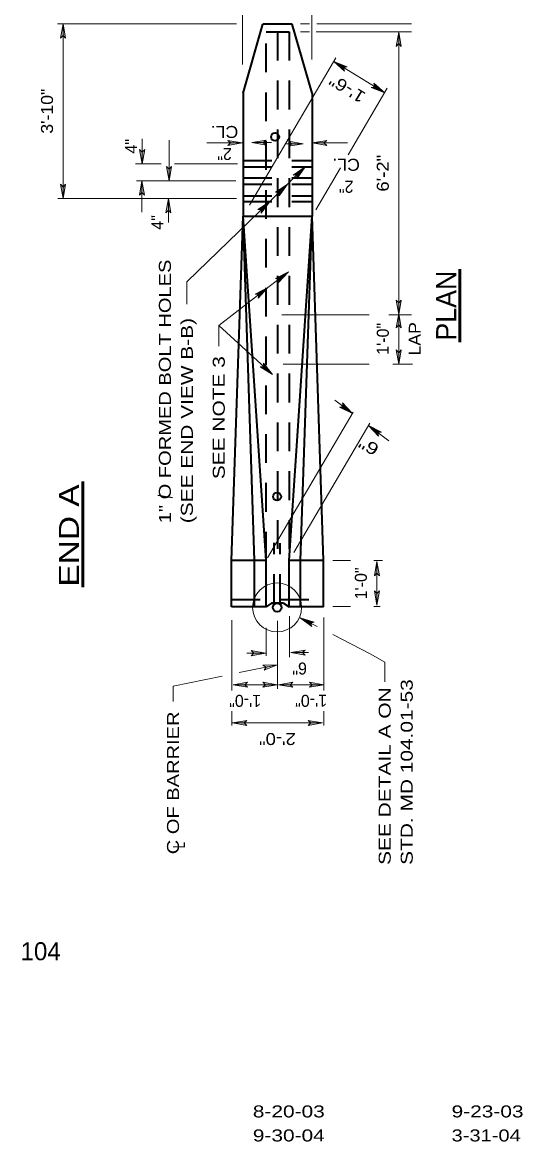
# Model space of a CAD drawing. Extents: x 12.6 to 19.4, y 6.1 to 16.3.
# Drawn here: x 12.57 to 15.07, y 6.25 to 11.84 of the extents above; entities that cross this region are included whole.
import ezdxf
from ezdxf.enums import TextEntityAlignment as Align

# ---------------------------------------------------------------- set-up
doc = ezdxf.new("R2010")
doc.units = 0
doc.header["$LTSCALE"] = 0.024
doc.linetypes.add('LONG_DASHED', pattern=[7.5, 6, -1.5])
for name, color, linetype, lineweight in [('1', 7, 'Continuous', 35), ('10', 7, 'Continuous', 13), ('12', 7, 'Continuous', 53), ('13', 7, 'Continuous', 53)]:
    doc.layers.add(name, color=color, linetype=linetype, lineweight=lineweight)

msp = doc.modelspace()

# ---------------------------------------------------------------- hatches: boundary and pattern name
at = {"layer": '10'}
for points in [[(12.7624, 11.7651), (12.775, 11.8366), (12.7876, 11.7651), (12.775, 11.7786)], [(14.4403, 11.724), (14.4529, 11.7955), (14.4655, 11.724), (14.4529, 11.7375)], [(14.1823, 11.6), (14.128, 11.6482), (14.1955, 11.6215), (14.1774, 11.6178)], [(14.3284, 11.5397), (14.3827, 11.4915), (14.3152, 11.5182), (14.3333, 11.5219)], [(13.5988, 11.2538), (13.6703, 11.2412), (13.5988, 11.2286), (13.6123, 11.2412)], [(13.7894, 11.2304), (13.7179, 11.243), (13.7894, 11.2556), (13.7759, 11.243)], [(13.9038, 11.2503), (13.9753, 11.2377), (13.9038, 11.2251), (13.9173, 11.2377)], [(14.0926, 11.2286), (14.0211, 11.2412), (14.0926, 11.2538), (14.0791, 11.2412)], [(13.1831, 11.2089), (13.1705, 11.1374), (13.1579, 11.2089), (13.1705, 11.1954)], [(13.3179, 11.1235), (13.3053, 11.052), (13.2927, 11.1235), (13.3053, 11.11)], [(13.9256, 11.0809), (13.9857, 11.1216), (13.9431, 11.0628), (13.9441, 11.0812)], [(12.7876, 11.0346), (12.775, 10.9631), (12.7624, 11.0346), (12.775, 11.0211)], [(13.1569, 10.9805), (13.1695, 11.052), (13.1821, 10.9805), (13.1695, 10.994)], [(13.8372, 10.9952), (13.8973, 11.0359), (13.8547, 10.9771), (13.8557, 10.9955)], [(13.2889, 10.8916), (13.3015, 10.9631), (13.3141, 10.8916), (13.3015, 10.9051)], [(13.7478, 10.9085), (13.8079, 10.9492), (13.7653, 10.8904), (13.7662, 10.9088)], [(13.8366, 10.5636), (13.9012, 10.5967), (13.8518, 10.5435), (13.855, 10.5617)], [(13.7348, 10.4854), (13.799, 10.5193), (13.7503, 10.4655), (13.7532, 10.4837)], [(14.4655, 10.4559), (14.4529, 10.3844), (14.4403, 10.4559), (14.4529, 10.4424)], [(14.4403, 10.3182), (14.4529, 10.3897), (14.4655, 10.3182), (14.4529, 10.3317)], [(14.4655, 10.2068), (14.4529, 10.1353), (14.4403, 10.2068), (14.4529, 10.1933)], [(13.7776, 10.1417), (13.822, 10.0843), (13.7606, 10.1231), (13.7791, 10.1233)], [(14.1716, 9.9421), (14.2215, 9.8893), (14.1566, 9.9219), (14.175, 9.9239)], [(14.3513, 9.7767), (14.3016, 9.8296), (14.3664, 9.7969), (14.3481, 9.7949)], [(14.3308, 9.0777), (14.3434, 9.1492), (14.356, 9.0777), (14.3434, 9.0912)], [(14.356, 9.0035), (14.3434, 8.932), (14.3308, 9.0035), (14.3434, 8.99)], [(14.0184, 8.8249), (13.9607, 8.869), (14.03, 8.8473), (14.0122, 8.8423)], [(13.7147, 8.7045), (13.7862, 8.6919), (13.7147, 8.6793), (13.7282, 8.6919)], [(13.9855, 8.6825), (13.914, 8.6951), (13.9855, 8.7077), (13.972, 8.6951)], [(13.7743, 8.6323), (13.8469, 8.6344), (13.7794, 8.6077), (13.7901, 8.6227)], [(13.6964, 8.5213), (13.6249, 8.5339), (13.6964, 8.5465), (13.6829, 8.5339)], [(13.7737, 8.5465), (13.8452, 8.5339), (13.7737, 8.5213), (13.7872, 8.5339)], [(13.9232, 8.5213), (13.8517, 8.5339), (13.9232, 8.5465), (13.9097, 8.5339)], [(14.0064, 8.5465), (14.0779, 8.5339), (14.0064, 8.5213), (14.0199, 8.5339)], [(13.6932, 8.3305), (13.6217, 8.3431), (13.6932, 8.3557), (13.6797, 8.3431)], [(13.9998, 8.3557), (14.0713, 8.3431), (13.9998, 8.3305), (14.0133, 8.3431)]]:
    msp.add_hatch(color=256, dxfattribs=at).paths.add_polyline_path(points)

# ---------------------------------------------------------------- linework, layer by layer
at = {"layer": '1'}
for p, q in [((13.6744, 11.4896), (13.7734, 11.8351)), ((13.9206, 11.8351), (13.7743, 11.8351)), ((14.0198, 11.4896), (13.9206, 11.8351)), ((14.0198, 11.4896), (14.0198, 10.8755)), ((13.7895, 9.1542), (13.6744, 10.8755)), ((13.9047, 9.1542), (14.0198, 10.8755)), ((13.9622, 9.1542), (14.0198, 10.8755)), ((13.7895, 9.1542), (13.6168, 9.1542)), ((13.7895, 8.9239), (13.7895, 9.1542)), ((13.9047, 8.9239), (13.9047, 9.1542)), ((14.0773, 9.1542), (13.9108, 9.1542)), ((13.9622, 8.9239), (13.9622, 9.1542)), ((13.7895, 8.9239), (13.6168, 8.9239)), ((13.8767, 8.9424), (13.8471, 8.9424)), ((13.8767, 8.9424), (13.9047, 8.9239)), ((14.0773, 8.9239), (13.9047, 8.9239))]:
    msp.add_line(p, q, dxfattribs=at)
at = {"layer": '1', "linetype": 'LONG_DASHED'}
for p, q in [((13.8471, 11.7968), (13.8471, 9.1542)), ((13.6744, 11.1536), (14.0198, 11.1536)), ((13.6744, 11.1224), (14.0198, 11.1224)), ((13.6744, 11.067), (14.0198, 11.067)), ((13.6744, 11.0359), (14.0198, 11.0359)), ((13.6744, 10.977), (14.0198, 10.977)), ((13.6744, 10.9492), (14.0198, 10.9492)), ((13.8302, 8.9424), (13.8302, 9.2428)), ((13.8596, 8.9424), (13.8596, 9.2416)), ((13.6158, 8.9593), (14.0773, 8.9593))]:
    msp.add_line(p, q, dxfattribs=at)
msp.add_lwpolyline([(13.7895, 9.1542), (13.7895, 11.7968), (13.9047, 11.7968), (13.9047, 9.1542)], dxfattribs=at)
at = {"layer": '1'}
for points in [[(13.6744, 11.4896), (13.6744, 10.8755), (14.0198, 10.8755)], [(13.6168, 8.9239), (13.6168, 9.1542), (13.6744, 10.8755)], [(13.732, 8.9239), (13.732, 9.1542), (13.6744, 10.8755)], [(14.0773, 8.9239), (14.0773, 9.1542), (14.0198, 10.8755)], [(13.8471, 8.9424), (13.8175, 8.9424), (13.7895, 8.9239)]]:
    msp.add_lwpolyline(points, dxfattribs=at)
for centre, radius in [((13.8347, 11.2714), 0.0197), ((13.8446, 9.4745), 0.0197), ((13.8449, 8.9207), 0.0216)]:
    msp.add_circle(centre, radius, dxfattribs=at)
at = {"layer": '10'}
for p, q in [((13.6715, 11.6327), (13.6715, 12.3353)), ((14.0189, 11.659), (14.0189, 12.3353)), ((12.7474, 11.8366), (13.6423, 11.8366)), ((12.775, 11.8366), (12.7624, 11.7651)), ((12.775, 10.9631), (12.775, 11.8366)), ((12.775, 11.8366), (12.7876, 11.7651)), ((14.0074, 11.8366), (13.9616, 11.8366)), ((14.5163, 11.8366), (14.0427, 11.8366)), ((14.0074, 11.7968), (13.9616, 11.7968)), ((14.5163, 11.7968), (14.0392, 11.7968)), ((14.4529, 11.7955), (14.4403, 11.724)), ((14.4529, 11.7955), (14.4529, 10.3844)), ((14.4529, 11.7955), (14.4655, 11.724)), ((14.1389, 11.666), (13.7067, 10.9305)), ((14.3827, 11.4915), (14.128, 11.6482)), ((14.128, 11.6482), (14.1823, 11.6)), ((14.128, 11.6482), (14.1955, 11.6215)), ((14.3827, 11.4915), (14.3284, 11.5397)), ((14.3956, 11.515), (14.1998, 11.1817)), ((14.3827, 11.4915), (14.3152, 11.5182)), ((13.1705, 11.1374), (13.1705, 11.2621)), ((13.3053, 11.2549), (13.3053, 11.052)), ((13.4941, 11.2412), (13.6703, 11.2412)), ((13.6703, 11.2412), (13.5988, 11.2538)), ((13.6703, 11.2412), (13.5988, 11.2286)), ((13.7179, 11.243), (13.7894, 11.2556)), ((13.7179, 11.243), (13.8164, 11.243)), ((13.7179, 11.243), (13.7894, 11.2304)), ((13.9753, 11.2377), (13.9038, 11.2503)), ((14.0211, 11.2412), (14.0926, 11.2538)), ((14.0211, 11.2412), (14.1973, 11.2412)), ((14.0211, 11.2412), (14.0926, 11.2286)), ((13.1705, 11.1374), (13.1579, 11.2089)), ((13.1705, 11.1374), (13.1831, 11.2089)), ((13.8925, 11.2377), (13.9753, 11.2377)), ((13.9753, 11.2377), (13.9038, 11.2251)), ((13.1371, 11.1374), (13.2659, 11.1374)), ((13.6469, 11.1374), (13.3326, 11.1374)), ((13.3053, 11.052), (13.2927, 11.1235)), ((13.3053, 11.052), (13.3179, 11.1235)), ((13.9857, 11.1216), (13.8973, 11.0359)), ((13.9857, 11.1216), (13.9256, 11.0809)), ((13.9857, 11.1216), (13.9431, 11.0628)), ((14.162, 11.1174), (14.0383, 10.9069)), ((12.775, 10.9631), (12.7624, 11.0346)), ((12.775, 10.9631), (12.7876, 11.0346)), ((13.1416, 11.052), (13.6388, 11.052)), ((13.1695, 11.052), (13.1569, 10.9805)), ((13.1695, 11.052), (13.1695, 10.8947)), ((13.1695, 11.052), (13.1821, 10.9805)), ((13.8079, 10.9492), (13.8973, 11.0359)), ((13.8973, 11.0359), (13.8372, 10.9952)), ((13.8447, 10.9996), (13.8973, 11.0359)), ((13.8973, 11.0359), (13.8547, 10.9771)), ((13.8593, 10.9845), (13.8973, 11.0359)), ((12.7483, 10.9631), (13.6415, 10.9631)), ((13.3015, 10.9631), (13.2889, 10.8916)), ((13.3015, 10.8442), (13.3015, 10.9631)), ((13.3015, 10.9631), (13.3141, 10.8916)), ((13.8447, 10.9996), (13.8577, 10.9975)), ((13.8593, 10.9845), (13.8577, 10.9975)), ((13.8079, 10.9492), (13.394, 10.5481)), ((13.8079, 10.9492), (13.7478, 10.9085)), ((13.7554, 10.9129), (13.8079, 10.9492)), ((13.7554, 10.9129), (13.7683, 10.9109)), ((13.8079, 10.9492), (13.7653, 10.8904)), ((13.77, 10.8979), (13.7683, 10.9109)), ((13.77, 10.8979), (13.8079, 10.9492)), ((13.9012, 10.5967), (13.8366, 10.5636)), ((13.9012, 10.5967), (13.8518, 10.5435)), ((13.394, 10.4362), (13.394, 10.5481)), ((13.799, 10.5193), (13.7348, 10.4854)), ((13.799, 10.5193), (13.7503, 10.4655)), ((14.4529, 10.3844), (14.4403, 10.4559)), ((14.4529, 10.3844), (14.4655, 10.4559)), ((14.3053, 10.3831), (13.8682, 10.3831)), ((14.5163, 10.3831), (14.4029, 10.3831)), ((14.4529, 10.3897), (14.4403, 10.3182)), ((14.4529, 10.3897), (14.4529, 10.1353)), ((14.4529, 10.3897), (14.4655, 10.3182)), ((13.5534, 10.2259), (13.5534, 10.3285)), ((13.5534, 10.3285), (13.822, 10.0843)), ((14.4529, 10.1353), (14.4403, 10.2068)), ((14.4529, 10.1353), (14.4655, 10.2068)), ((13.822, 10.0843), (13.7606, 10.1231)), ((13.822, 10.0843), (13.7776, 10.1417)), ((14.3053, 10.1353), (13.8748, 10.1353)), ((14.5216, 10.1353), (14.4235, 10.1353)), ((14.1326, 9.9554), (14.2215, 9.8893)), ((14.2215, 9.8893), (14.1566, 9.9219)), ((14.2215, 9.8893), (14.1716, 9.9421)), ((14.2254, 9.8959), (13.7973, 9.1675)), ((13.9283, 9.1945), (14.3084, 9.8412)), ((14.4035, 9.7535), (14.3016, 9.8296)), ((14.3016, 9.8296), (14.3513, 9.7767)), ((14.3016, 9.8296), (14.3664, 9.7969)), ((14.1238, 9.1542), (14.211, 9.1542)), ((14.3281, 9.1542), (14.3716, 9.1542)), ((14.3434, 9.1492), (14.3308, 9.0777)), ((14.3434, 8.932), (14.3434, 9.1492)), ((14.3434, 9.1492), (14.356, 9.0777)), ((14.3434, 8.932), (14.3308, 9.0035)), ((14.3434, 8.932), (14.356, 9.0035)), ((14.1238, 8.9254), (14.211, 8.9254)), ((14.3281, 8.9254), (14.3601, 8.9254)), ((13.6191, 8.8563), (13.6191, 8.5053)), ((13.8469, 8.8531), (13.8469, 8.5142)), ((13.9075, 8.876), (13.9075, 8.6717)), ((13.9607, 8.869), (14.0449, 8.8254)), ((13.9607, 8.869), (14.0184, 8.8249)), ((13.9607, 8.869), (14.03, 8.8473)), ((14.0779, 8.8695), (14.0779, 8.5053)), ((13.7895, 8.8181), (13.7895, 8.6785)), ((14.3098, 8.6884), (14.1234, 8.7849)), ((13.7862, 8.6919), (13.6929, 8.6919)), ((13.7862, 8.6919), (13.7147, 8.7045)), ((13.7862, 8.6919), (13.7147, 8.6793)), ((13.914, 8.6951), (13.9855, 8.7077)), ((13.914, 8.6951), (14.0011, 8.6951)), ((13.914, 8.6951), (13.9855, 8.6825)), ((14.3098, 8.6884), (14.3825, 8.6464)), ((13.8469, 8.6344), (13.6558, 8.5951)), ((13.8469, 8.6344), (13.7743, 8.6323)), ((13.8469, 8.6344), (13.7794, 8.6077)), ((14.3825, 8.5488), (14.3825, 8.6464)), ((13.3246, 8.5267), (13.57, 8.5774)), ((13.3246, 8.5267), (13.3246, 8.4504)), ((13.6249, 8.5339), (13.6964, 8.5465)), ((13.8452, 8.5339), (13.6249, 8.5339)), ((13.6249, 8.5339), (13.6964, 8.5213)), ((13.8452, 8.5339), (13.7737, 8.5465)), ((13.8452, 8.5339), (13.7737, 8.5213)), ((13.8517, 8.5339), (13.9232, 8.5465)), ((13.8517, 8.5339), (14.0779, 8.5339)), ((13.8517, 8.5339), (13.9232, 8.5213)), ((14.0779, 8.5339), (14.0064, 8.5465)), ((14.0779, 8.5339), (14.0064, 8.5213)), ((13.6191, 8.4028), (13.6191, 8.33)), ((14.0779, 8.4028), (14.0779, 8.33)), ((13.6217, 8.3431), (13.6932, 8.3557)), ((14.0713, 8.3431), (13.6217, 8.3431)), ((13.6217, 8.3431), (13.6932, 8.3305)), ((14.0713, 8.3431), (13.9998, 8.3557)), ((14.0713, 8.3431), (13.9998, 8.3305))]:
    msp.add_line(p, q, dxfattribs=at)
at = {"layer": '10', "lineweight": 25}
msp.add_line((13.3217, 9.4688), (13.2486, 9.4791), dxfattribs=at)
at = {"layer": '10'}
for points in [[(12.7624, 11.7651), (12.775, 11.8366), (12.7876, 11.7651), (12.775, 11.7786)], [(14.4403, 11.724), (14.4529, 11.7955), (14.4655, 11.724), (14.4529, 11.7375)], [(14.1823, 11.6), (14.128, 11.6482), (14.1955, 11.6215), (14.1774, 11.6178)], [(14.3284, 11.5397), (14.3827, 11.4915), (14.3152, 11.5182), (14.3333, 11.5219)], [(13.5988, 11.2538), (13.6703, 11.2412), (13.5988, 11.2286), (13.6123, 11.2412)], [(13.7894, 11.2304), (13.7179, 11.243), (13.7894, 11.2556), (13.7759, 11.243)], [(13.9038, 11.2503), (13.9753, 11.2377), (13.9038, 11.2251), (13.9173, 11.2377)], [(14.0926, 11.2286), (14.0211, 11.2412), (14.0926, 11.2538), (14.0791, 11.2412)], [(13.1831, 11.2089), (13.1705, 11.1374), (13.1579, 11.2089), (13.1705, 11.1954)], [(13.3179, 11.1235), (13.3053, 11.052), (13.2927, 11.1235), (13.3053, 11.11)], [(13.9256, 11.0809), (13.9857, 11.1216), (13.9431, 11.0628), (13.9441, 11.0812)], [(12.7876, 11.0346), (12.775, 10.9631), (12.7624, 11.0346), (12.775, 11.0211)], [(13.1569, 10.9805), (13.1695, 11.052), (13.1821, 10.9805), (13.1695, 10.994)], [(13.8372, 10.9952), (13.8973, 11.0359), (13.8547, 10.9771), (13.8557, 10.9955)], [(13.2889, 10.8916), (13.3015, 10.9631), (13.3141, 10.8916), (13.3015, 10.9051)], [(13.7478, 10.9085), (13.8079, 10.9492), (13.7653, 10.8904), (13.7662, 10.9088)], [(13.8366, 10.5636), (13.9012, 10.5967), (13.8518, 10.5435), (13.855, 10.5617)], [(13.7348, 10.4854), (13.799, 10.5193), (13.7503, 10.4655), (13.7532, 10.4837)], [(14.4655, 10.4559), (14.4529, 10.3844), (14.4403, 10.4559), (14.4529, 10.4424)], [(14.4403, 10.3182), (14.4529, 10.3897), (14.4655, 10.3182), (14.4529, 10.3317)], [(14.4655, 10.2068), (14.4529, 10.1353), (14.4403, 10.2068), (14.4529, 10.1933)], [(13.7776, 10.1417), (13.822, 10.0843), (13.7606, 10.1231), (13.7791, 10.1233)], [(14.1716, 9.9421), (14.2215, 9.8893), (14.1566, 9.9219), (14.175, 9.9239)], [(14.3513, 9.7767), (14.3016, 9.8296), (14.3664, 9.7969), (14.3481, 9.7949)], [(14.3308, 9.0777), (14.3434, 9.1492), (14.356, 9.0777), (14.3434, 9.0912)], [(14.356, 9.0035), (14.3434, 8.932), (14.3308, 9.0035), (14.3434, 8.99)], [(14.0184, 8.8249), (13.9607, 8.869), (14.03, 8.8473), (14.0122, 8.8423)], [(13.7147, 8.7045), (13.7862, 8.6919), (13.7147, 8.6793), (13.7282, 8.6919)], [(13.9855, 8.6825), (13.914, 8.6951), (13.9855, 8.7077), (13.972, 8.6951)], [(13.7743, 8.6323), (13.8469, 8.6344), (13.7794, 8.6077), (13.7901, 8.6227)], [(13.6964, 8.5213), (13.6249, 8.5339), (13.6964, 8.5465), (13.6829, 8.5339)], [(13.7737, 8.5465), (13.8452, 8.5339), (13.7737, 8.5213), (13.7872, 8.5339)], [(13.9232, 8.5213), (13.8517, 8.5339), (13.9232, 8.5465), (13.9097, 8.5339)], [(14.0064, 8.5465), (14.0779, 8.5339), (14.0064, 8.5213), (14.0199, 8.5339)], [(13.6932, 8.3305), (13.6217, 8.3431), (13.6932, 8.3557), (13.6797, 8.3431)], [(13.9998, 8.3557), (14.0713, 8.3431), (13.9998, 8.3305), (14.0133, 8.3431)]]:
    msp.add_lwpolyline(points, close=True, dxfattribs=at)
for points in [[(12.7624, 11.7651), (12.775, 11.7786), (12.7876, 11.7651)], [(14.4403, 11.724), (14.4529, 11.7375), (14.4655, 11.724)], [(14.1823, 11.6), (14.1774, 11.6178), (14.1955, 11.6215)], [(14.3284, 11.5397), (14.3333, 11.5219), (14.3152, 11.5182)], [(13.5988, 11.2538), (13.6123, 11.2412), (13.5988, 11.2286)], [(13.7894, 11.2304), (13.7759, 11.243), (13.7894, 11.2556)], [(13.9038, 11.2503), (13.9173, 11.2377), (13.9038, 11.2251)], [(14.0926, 11.2286), (14.0791, 11.2412), (14.0926, 11.2538)], [(13.1831, 11.2089), (13.1705, 11.1954), (13.1579, 11.2089)], [(13.3179, 11.1235), (13.3053, 11.11), (13.2927, 11.1235)], [(13.9256, 11.0809), (13.9441, 11.0812), (13.9431, 11.0628)], [(12.7876, 11.0346), (12.775, 11.0211), (12.7624, 11.0346)], [(13.1569, 10.9805), (13.1695, 10.994), (13.1821, 10.9805)], [(13.8372, 10.9952), (13.8557, 10.9955), (13.8547, 10.9771)], [(13.7478, 10.9085), (13.7662, 10.9088), (13.7653, 10.8904)], [(13.2889, 10.8916), (13.3015, 10.9051), (13.3141, 10.8916)], [(13.5534, 10.3285), (13.799, 10.5193), (13.9012, 10.5967)], [(13.8366, 10.5636), (13.855, 10.5617), (13.8518, 10.5435)], [(13.7348, 10.4854), (13.7532, 10.4837), (13.7503, 10.4655)], [(14.4655, 10.4559), (14.4529, 10.4424), (14.4403, 10.4559)], [(14.4403, 10.3182), (14.4529, 10.3317), (14.4655, 10.3182)], [(14.4655, 10.2068), (14.4529, 10.1933), (14.4403, 10.2068)], [(13.7776, 10.1417), (13.7791, 10.1233), (13.7606, 10.1231)], [(14.1716, 9.9421), (14.175, 9.9239), (14.1566, 9.9219)], [(14.3513, 9.7767), (14.3481, 9.7949), (14.3664, 9.7969)], [(14.3308, 9.0777), (14.3434, 9.0912), (14.356, 9.0777)], [(14.356, 9.0035), (14.3434, 8.99), (14.3308, 9.0035)], [(14.0184, 8.8249), (14.0122, 8.8423), (14.03, 8.8473)], [(13.7147, 8.7045), (13.7282, 8.6919), (13.7147, 8.6793)], [(13.9855, 8.6825), (13.972, 8.6951), (13.9855, 8.7077)], [(13.7743, 8.6323), (13.7901, 8.6227), (13.7794, 8.6077)], [(13.6964, 8.5213), (13.6829, 8.5339), (13.6964, 8.5465)], [(13.7737, 8.5465), (13.7872, 8.5339), (13.7737, 8.5213)], [(13.9232, 8.5213), (13.9097, 8.5339), (13.9232, 8.5465)], [(14.0064, 8.5465), (14.0199, 8.5339), (14.0064, 8.5213)], [(13.6932, 8.3305), (13.6797, 8.3431), (13.6932, 8.3557)], [(13.9998, 8.3557), (14.0133, 8.3431), (13.9998, 8.3305)]]:
    msp.add_lwpolyline(points, dxfattribs=at)
msp.add_circle((13.8449, 8.9207), 0.1223, dxfattribs=at)
at = {"layer": '12'}
for p, q in [((14.7584, 10.2466), (14.7584, 10.6103)), ((12.8733, 9.0224), (12.8733, 9.5494))]:
    msp.add_line(p, q, dxfattribs=at)

# ---------------------------------------------------------------- texts
for s, height, rotation, width, p in [('1\'-6"', 0.06, 148.388, 1.2, (14.2111, 11.5383)), ('3\'-10"', 0.06, 90, 1.1, (12.725, 11.3999)), ('CL.', 0.06, 180, 1.1, (13.5823, 11.3262)), ('CL.', 0.06, 180, 1.1, (14.1901, 11.1623)), ('6\'-2"', 0.06, 90, 1.15, (14.4029, 11.09)), ('LAP', 0.06, 90, 1.1, (14.5629, 10.2625)), ('6"', 0.06, 150, 1.35, (14.3181, 9.7518)), ('END A', 0.1, 90, 1.25, (12.8545, 9.2797)), ('2\'-0"', 0.06, 180, 1.15, (13.8465, 8.293))]:
    msp.add_text(s, height=height, rotation=rotation, dxfattribs=dict(at, width=width)).set_placement(p, align=Align.CENTER)
for s, height, rotation, p in [('4"', 0.06, 90, (13.1455, 11.2247)), ('2"', 0.06, 180, (13.5822, 11.2162)), ('2"', 0.06, 180, (14.1901, 11.0523)), ('4"', 0.06, 90, (13.2765, 10.8442)), ('PLAN', 0.1, 90, (14.7396, 10.4284)), ('1\'-0"', 0.06, 90, (14.4029, 10.2625)), ('1\'-0"', 0.06, 90, (14.2934, 9.0406)), ('6"', 0.06, 180, (13.9575, 8.645)), ('1\'-0"', 0.06, 180, (13.685, 8.4837)), ('1\'-0"', 0.06, 180, (14.0147, 8.4838))]:
    msp.add_text(s, height=height, rotation=rotation, dxfattribs=at).set_placement(p, align=Align.CENTER)
for s, width, p in [('1" O FORMED BOLT HOLES', 1.25, (13.314, 9.3412)), ('(SEE END VIEW B-B)', 1.3, (13.424, 9.3412)), ('STD. MD 104.01-53', 1.3, (14.5225, 7.6342)), ('SEE DETAIL A ON', 1.3, (14.4125, 7.6342))]:
    msp.add_text(s, height=0.06, rotation=90, dxfattribs=dict(at, width=width)).set_placement(p)
for s, width, p in [('SEE NOTE 3', 1.3, (13.5834, 10.1759)), ('C OF BARRIER', 1.25, (13.3546, 8.4004)), ('L', 0.75, (13.3845, 7.7495))]:
    msp.add_text(s, height=0.06, rotation=90, dxfattribs=dict(at, width=width)).set_placement(p, align=Align.RIGHT)
at = {"layer": '13'}
msp.add_text('104', height=0.09, dxfattribs=at).set_placement((12.6632, 7.1575), align=Align.CENTER)
for s, width, p in [('8-20-03', 1.3, (13.7235, 6.3721)), ('9-23-03', 1.3, (14.7167, 6.3721)), ('9-30-04', 1.3, (13.7235, 6.2521)), ('3-31-04', 1.25, (14.7167, 6.2521))]:
    msp.add_text(s, height=0.06, dxfattribs=dict(at, width=width)).set_placement(p)

doc.saveas('drawing.dxf')
